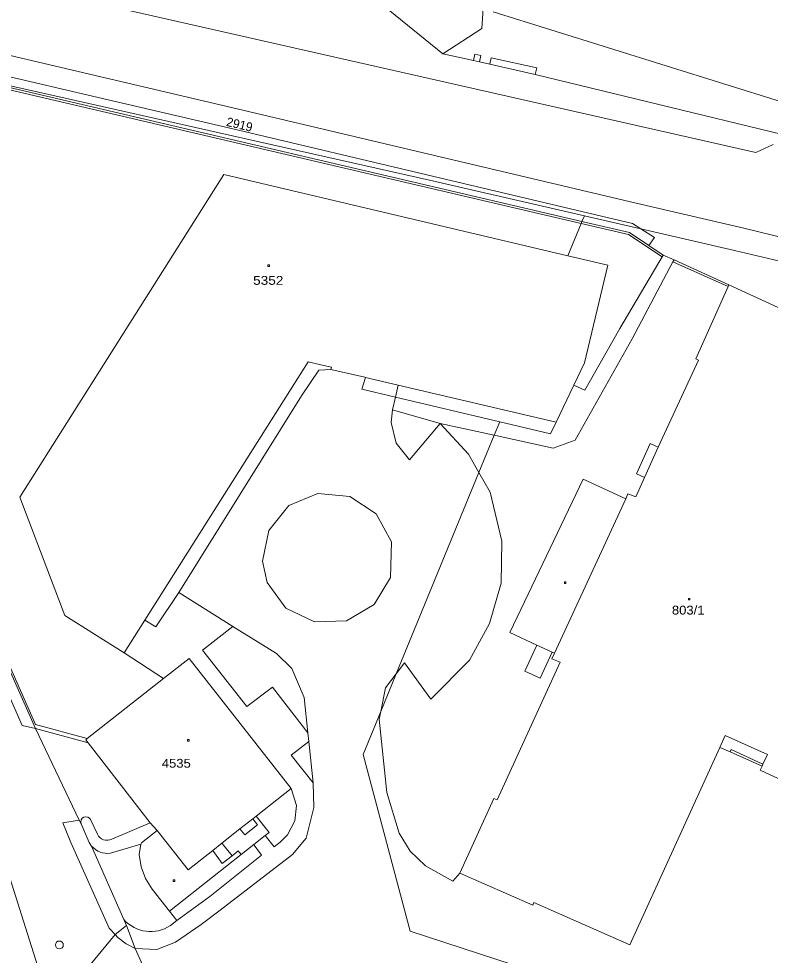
# Model space of a CAD drawing. Extents: x -630464 to -630140, y -1004543 to -1004208.
# Drawn here: x -630402.7 to -630330.5, y -1004346.3 to -1004256.3 of the extents above; entities that cross this region are included whole.
import ezdxf

# ---------------------------------------------------------------- set-up
doc = ezdxf.new("R2010")
doc.units = 0
doc.header["$LTSCALE"] = 0.34
for name, color, linetype, lineweight in [('1', 7, 'Continuous', 13), ('2', 7, 'Continuous', 13), ('25', 7, 'Continuous', 13), ('28', 7, 'Continuous', 13)]:
    doc.layers.add(name, color=color, linetype=linetype, lineweight=lineweight)
doc.layers.add('14', color=7, linetype='Continuous')
doc.layers.add('15', color=7, linetype='Continuous')

msp = doc.modelspace()

# ---------------------------------------------------------------- linework, layer by layer
at = {"layer": '1'}
for p, q in [((-630358.18, -1004257.25), (-630356.54, -1004231.37)), ((-630361.95, -1004259.68), (-630358.18, -1004257.25)), ((-630361.95, -1004259.68), (-630359, -1004260.33)), ((-630408.19, -1004261.71), (-630363.23, -1004271.82)), ((-630394.38, -1004262), (-630381.7, -1004264.98)), ((-630363.23, -1004271.82), (-630348.34, -1004275.25)), ((-630349.92, -1004279.08), (-630348.64, -1004275.98)), ((-630342.92, -1004276.5), (-630333.92, -1004278.57)), ((-630349.92, -1004279.08), (-630346.1, -1004279.98)), ((-630333.92, -1004278.57), (-630314.14, -1004283.28)), ((-630348.33, -1004289.39), (-630346.1, -1004279.98)), ((-630349.35, -1004291.51), (-630348.33, -1004289.39)), ((-630369.72, -1004291.92), (-630369.38, -1004290.78)), ((-630369.45, -1004290.77), (-630369.38, -1004290.78)), ((-630369.72, -1004291.92), (-630366.5, -1004292.68)), ((-630387.32, -1004311.45), (-630375.53, -1004292.54)), ((-630366.5, -1004292.68), (-630356.47, -1004295.05)), ((-630389.53, -1004314.74), (-630387.32, -1004311.45)), ((-630392.55, -1004317.25), (-630390.56, -1004314.1)), ((-630390.56, -1004314.1), (-630389.53, -1004314.74)), ((-630369.6, -1004327.01), (-630365.09, -1004344)), ((-630379.88, -1004332.94), (-630376.52, -1004330.29)), ((-630379.88, -1004332.94), (-630378.62, -1004334.51)), ((-630390.05, -1004333.58), (-630389.39, -1004334.31)), ((-630379, -1004334.81), (-630378.62, -1004334.51)), ((-630388.2, -1004342.09), (-630381.31, -1004336.63)), ((-630390.5, -1004338.94), (-630389.87, -1004339.97)), ((-630389.87, -1004339.97), (-630388.2, -1004342.09)), ((-630392.58, -1004342.89), (-630392.33, -1004343.45)), ((-630365.09, -1004344), (-630343.21, -1004351.12)), ((-630397.75, -1004349.57), (-630393.43, -1004344.32))]:
    msp.add_line(p, q, dxfattribs=at)
for points in [[(-630396.18, -1004252.07), (-630386.63, -1004248.4), (-630371.62, -1004251.8), (-630361.95, -1004259.68)], [(-630421.48, -1004257.69), (-630421.1, -1004257.42), (-630418.9, -1004256.48), (-630418.37, -1004256.39), (-630417.22, -1004256.61), (-630408.43, -1004258.7), (-630394.38, -1004262)], [(-630359, -1004260.33), (-630358.43, -1004260.46), (-630357.43, -1004260.68)], [(-630357.43, -1004260.68), (-630353.06, -1004261.66), (-630329.31, -1004267.44), (-630320.75, -1004269.74)], [(-630381.7, -1004264.98), (-630362.75, -1004269.45), (-630343.38, -1004274.04), (-630333.03, -1004276.43), (-630303.66, -1004283.61)], [(-630402.58, -1004302.3), (-630382.99, -1004271.28), (-630349.92, -1004279.08)], [(-630348.64, -1004275.98), (-630348.57, -1004275.81), (-630348.34, -1004275.25), (-630342.92, -1004276.5)], [(-630375.53, -1004292.54), (-630373.84, -1004290.08), (-630372.7, -1004290.01), (-630369.45, -1004290.77)], [(-630416.37, -1004290.21), (-630413.84, -1004296.07), (-630407.49, -1004310.15), (-630401.09, -1004324.53), (-630396.87, -1004333.33), (-630396.7, -1004333.68), (-630395.91, -1004335.47), (-630395.69, -1004335.82), (-630392.58, -1004342.89)], [(-630369.6, -1004327.01), (-630367.91, -1004322.89), (-630366.41, -1004319.26), (-630358.47, -1004299.92), (-630357, -1004296.34), (-630356.47, -1004295.05), (-630351.59, -1004296.2), (-630351.06, -1004295.08), (-630349.35, -1004291.51)], [(-630402.58, -1004302.3), (-630398.27, -1004313.66), (-630392.55, -1004317.25)], [(-630396.24, -1004325.6), (-630396.1, -1004325.48), (-630388.77, -1004319.7), (-630386.31, -1004317.78), (-630376.52, -1004330.29)], [(-630396.24, -1004325.6), (-630396.03, -1004325.9), (-630390.05, -1004333.58)], [(-630391.11, -1004336.62), (-630390.95, -1004335.65), (-630390.9, -1004335.51), (-630389.39, -1004334.31)], [(-630381.31, -1004336.63), (-630380.11, -1004335.68), (-630379, -1004334.81)], [(-630431.57, -1004347.96), (-630430.78, -1004347.84), (-630408.36, -1004344.42), (-630404.14, -1004336.97), (-630403.55, -1004338.86), (-630399.75, -1004350.85), (-630399.53, -1004351.54)], [(-630391.11, -1004336.62), (-630390.94, -1004337.81), (-630390.5, -1004338.94)], [(-630393.43, -1004344.32), (-630392.33, -1004343.45), (-630391.49, -1004345.66)], [(-630391.49, -1004345.66), (-630390.2, -1004348.57), (-630360.7, -1004381.74)]]:
    msp.add_lwpolyline(points, dxfattribs=at)
at = {"layer": '2'}
for p, q in [((-630416.92, -1004249.88), (-630331.87, -1004269.15)), ((-630357.09, -1004255.65), (-630329.39, -1004264.29)), ((-630358.43, -1004260.46), (-630358.29, -1004259.83)), ((-630357.43, -1004260.68), (-630357.29, -1004260.05)), ((-630357.29, -1004260.05), (-630352.92, -1004261.02)), ((-630408.68, -1004260.69), (-630395.06, -1004263.89)), ((-630353.06, -1004261.66), (-630352.92, -1004261.02)), ((-630409.01, -1004261.64), (-630348.57, -1004275.81)), ((-630408.92, -1004261.88), (-630348.64, -1004275.98)), ((-630395.06, -1004263.89), (-630382.13, -1004266.9)), ((-630382.13, -1004266.9), (-630362.92, -1004271.45)), ((-630331.87, -1004269.15), (-630330.2, -1004268.41)), ((-630362.92, -1004271.45), (-630343.72, -1004275.99)), ((-630348.64, -1004275.98), (-630344.1, -1004277.05)), ((-630348.57, -1004275.81), (-630344.02, -1004276.86)), ((-630343.72, -1004275.99), (-630342.92, -1004276.5)), ((-630342.92, -1004276.5), (-630341.61, -1004277.32)), ((-630344.1, -1004277.05), (-630340.87, -1004279.19)), ((-630344.02, -1004276.86), (-630342.14, -1004278.11)), ((-630342.14, -1004278.11), (-630341.61, -1004277.32)), ((-630342.14, -1004278.11), (-630340.77, -1004279.02)), ((-630344.94, -1004286.07), (-630340.87, -1004279.19)), ((-630343.74, -1004287.07), (-630339.83, -1004279.68)), ((-630339.83, -1004279.68), (-630339.72, -1004279.47)), ((-630339.83, -1004279.68), (-630334.51, -1004282.03)), ((-630339.72, -1004279.47), (-630334.45, -1004281.89)), ((-630337.64, -1004288.99), (-630334.51, -1004282.03)), ((-630348.29, -1004292.01), (-630344.94, -1004286.07)), ((-630349.21, -1004296.8), (-630343.74, -1004287.07)), ((-630390.56, -1004314.1), (-630374.88, -1004289.28)), ((-630374.88, -1004289.28), (-630373.66, -1004289.57)), ((-630337.64, -1004288.99), (-630337.37, -1004289.11)), ((-630373.66, -1004289.57), (-630372.65, -1004289.8)), ((-630372.7, -1004290.01), (-630372.65, -1004289.8)), ((-630369.38, -1004290.78), (-630366.22, -1004291.52)), ((-630366.5, -1004292.68), (-630366.22, -1004291.52)), ((-630366.22, -1004291.52), (-630351.06, -1004295.08)), ((-630349.35, -1004291.51), (-630348.29, -1004292.01)), ((-630366.79, -1004293.91), (-630366.5, -1004292.68)), ((-630366.92, -1004295.11), (-630366.79, -1004293.91)), ((-630366.79, -1004293.91), (-630362.19, -1004295.2)), ((-630366.92, -1004295.11), (-630366.43, -1004297.09)), ((-630365.14, -1004298.71), (-630362.19, -1004295.2)), ((-630362.19, -1004295.2), (-630357, -1004296.34)), ((-630362.19, -1004295.2), (-630359.48, -1004298.15)), ((-630357, -1004296.34), (-630351.33, -1004297.58)), ((-630366.43, -1004297.09), (-630365.14, -1004298.71)), ((-630351.33, -1004297.58), (-630349.21, -1004296.8)), ((-630343.34, -1004300.04), (-630342.03, -1004297.12)), ((-630359.48, -1004298.15), (-630358.47, -1004299.92)), ((-630342.57, -1004300.39), (-630341.26, -1004297.47)), ((-630358.47, -1004299.92), (-630357.39, -1004301.82)), ((-630343.34, -1004300.04), (-630342.57, -1004300.39)), ((-630355.49, -1004315.31), (-630348.45, -1004300.55)), ((-630348.45, -1004300.55), (-630344.37, -1004302.44)), ((-630343.4, -1004302.26), (-630342.57, -1004300.39)), ((-630357.39, -1004301.82), (-630356.26, -1004306.53)), ((-630376.75, -1004303.1), (-630373.94, -1004301.92)), ((-630373.94, -1004301.92), (-630370.88, -1004302.21)), ((-630370.88, -1004302.21), (-630368.33, -1004303.9)), ((-630351.22, -1004317.28), (-630344.37, -1004302.44)), ((-630344.37, -1004302.44), (-630344.15, -1004301.96)), ((-630344.15, -1004301.96), (-630343.4, -1004302.26)), ((-630378.66, -1004305.5), (-630376.75, -1004303.1)), ((-630368.33, -1004303.9), (-630366.86, -1004306.59)), ((-630379.27, -1004308.45), (-630378.66, -1004305.5)), ((-630366.96, -1004310.01), (-630366.86, -1004306.59)), ((-630356.35, -1004310.54), (-630356.26, -1004306.53)), ((-630379.27, -1004308.45), (-630378.81, -1004310.48)), ((-630407.31, -1004310.07), (-630401.07, -1004324.14)), ((-630378.81, -1004310.48), (-630377.02, -1004312.96)), ((-630368.55, -1004312.6), (-630366.96, -1004310.01)), ((-630357.45, -1004314.42), (-630356.35, -1004310.54)), ((-630387.32, -1004311.45), (-630382.11, -1004314.71)), ((-630371.21, -1004314.16), (-630368.55, -1004312.6)), ((-630377.02, -1004312.96), (-630374.26, -1004314.28)), ((-630374.26, -1004314.28), (-630371.21, -1004314.16)), ((-630359.38, -1004317.94), (-630357.45, -1004314.42)), ((-630385.03, -1004316.98), (-630382.11, -1004314.71)), ((-630382.11, -1004314.71), (-630377.92, -1004317.31)), ((-630355.49, -1004315.31), (-630352.9, -1004316.5)), ((-630385.03, -1004316.98), (-630380.76, -1004322.41)), ((-630354.05, -1004319), (-630352.9, -1004316.5)), ((-630352.9, -1004316.5), (-630351.45, -1004317.17)), ((-630352.6, -1004319.67), (-630351.45, -1004317.17)), ((-630351.45, -1004317.17), (-630351.22, -1004317.28)), ((-630392.55, -1004317.25), (-630388.77, -1004319.7)), ((-630377.92, -1004317.31), (-630376.44, -1004318.74)), ((-630363.1, -1004321.69), (-630359.38, -1004317.94)), ((-630351.47, -1004317.82), (-630351.22, -1004317.28)), ((-630351.47, -1004317.82), (-630350.66, -1004318.14)), ((-630376.44, -1004318.74), (-630375.27, -1004321.54)), ((-630366.41, -1004319.26), (-630365.61, -1004318.21)), ((-630365.61, -1004318.21), (-630363.1, -1004321.69)), ((-630356.71, -1004331.37), (-630350.66, -1004318.14)), ((-630367.46, -1004320.62), (-630366.41, -1004319.26)), ((-630354.05, -1004319), (-630352.6, -1004319.67)), ((-630380.76, -1004322.41), (-630378.31, -1004320.55)), ((-630378.31, -1004320.55), (-630374.91, -1004324.93)), ((-630375.27, -1004321.54), (-630374.91, -1004324.93)), ((-630402.35, -1004324.23), (-630401.09, -1004324.53)), ((-630401.07, -1004324.14), (-630396.1, -1004325.48)), ((-630368.05, -1004323.62), (-630367.33, -1004330.68)), ((-630401.09, -1004324.53), (-630396.03, -1004325.9)), ((-630374.91, -1004324.93), (-630374.83, -1004325.78)), ((-630376.5, -1004327.07), (-630374.83, -1004325.78)), ((-630374.83, -1004325.78), (-630374.41, -1004329.75)), ((-630376.5, -1004327.07), (-630374.41, -1004329.75)), ((-630343.96, -1004345.31), (-630335.33, -1004326.34)), ((-630334.33, -1004326.75), (-630335.33, -1004326.34)), ((-630334.33, -1004326.75), (-630334.24, -1004326.54)), ((-630334.33, -1004326.75), (-630331.27, -1004328.15)), ((-630334.24, -1004326.54), (-630331.18, -1004327.94)), ((-630331.18, -1004327.94), (-630330.76, -1004327.03)), ((-630331.27, -1004328.15), (-630331.18, -1004327.94)), ((-630331.44, -1004328.53), (-630331.27, -1004328.15)), ((-630331.44, -1004328.53), (-630326.84, -1004330.65)), ((-630374.41, -1004329.75), (-630374.35, -1004332.11)), ((-630376.52, -1004330.29), (-630376, -1004331.92)), ((-630367.33, -1004330.68), (-630366.15, -1004334.59)), ((-630360.32, -1004338.42), (-630357.03, -1004331.24)), ((-630357.03, -1004331.24), (-630356.71, -1004331.37)), ((-630376.16, -1004333.4), (-630376, -1004331.92)), ((-630375.06, -1004335.05), (-630374.35, -1004332.11)), ((-630398.45, -1004333.59), (-630396.87, -1004333.33)), ((-630395.78, -1004333.28), (-630395.13, -1004334.68)), ((-630381.43, -1004334.16), (-630380.21, -1004333.2)), ((-630380.21, -1004333.2), (-630379.88, -1004332.94)), ((-630380.21, -1004333.2), (-630379.74, -1004333.79)), ((-630393.75, -1004335.16), (-630390.05, -1004333.58)), ((-630383.16, -1004335.53), (-630381.43, -1004334.16)), ((-630381.43, -1004334.16), (-630380.96, -1004334.75)), ((-630380.96, -1004334.75), (-630379.74, -1004333.79)), ((-630376.85, -1004334.73), (-630376.16, -1004333.4)), ((-630389.39, -1004334.31), (-630386.41, -1004338.1)), ((-630379, -1004334.81), (-630378.15, -1004335.88)), ((-630377.57, -1004335.43), (-630376.85, -1004334.73)), ((-630376.37, -1004336.62), (-630375.06, -1004335.05)), ((-630366.15, -1004334.59), (-630365.07, -1004336.31)), ((-630393.88, -1004336.51), (-630390.95, -1004335.65)), ((-630384.05, -1004336.24), (-630383.16, -1004335.53)), ((-630383.16, -1004335.53), (-630383.13, -1004335.57)), ((-630378.15, -1004335.88), (-630377.57, -1004335.43)), ((-630386.41, -1004338.1), (-630384.05, -1004336.24)), ((-630384.34, -1004340.68), (-630379.35, -1004336.69)), ((-630384.05, -1004336.24), (-630383.14, -1004337.5)), ((-630383.34, -1004341.99), (-630376.37, -1004336.62)), ((-630383.14, -1004337.5), (-630382.18, -1004336.75)), ((-630381.59, -1004336.28), (-630381.31, -1004336.63)), ((-630365.07, -1004336.31), (-630363.62, -1004337.71)), ((-630363.62, -1004337.71), (-630360.98, -1004339.19)), ((-630360.98, -1004339.19), (-630360.32, -1004338.42)), ((-630360.32, -1004338.42), (-630353.28, -1004341.51)), ((-630387.51, -1004342.98), (-630384.34, -1004340.68)), ((-630353.28, -1004341.51), (-630353.19, -1004341.25)), ((-630353.19, -1004341.25), (-630343.96, -1004345.31)), ((-630388.2, -1004342.09), (-630387.51, -1004342.98)), ((-630385.15, -1004343.35), (-630383.34, -1004341.99)), ((-630388.12, -1004343.46), (-630387.51, -1004342.98)), ((-630394.01, -1004343.71), (-630393.43, -1004344.32)), ((-630387.63, -1004345.05), (-630385.15, -1004343.35)), ((-630389.43, -1004345.76), (-630387.63, -1004345.05)), ((-630392.38, -1004345.21), (-630391.49, -1004345.66)), ((-630391.49, -1004345.66), (-630389.43, -1004345.76))]:
    msp.add_line(p, q, dxfattribs=at)
for points in [[(-630359, -1004260.33), (-630358.86, -1004259.7), (-630358.29, -1004259.83)], [(-630427.64, -1004266.74), (-630427.45, -1004267.49), (-630427.28, -1004267.99), (-630427.06, -1004267.9), (-630402.35, -1004324.23)], [(-630340.87, -1004279.19), (-630340.77, -1004279.02), (-630339.72, -1004279.47)], [(-630334.51, -1004282.03), (-630334.45, -1004281.89), (-630327.34, -1004285.15)], [(-630342.03, -1004297.12), (-630341.26, -1004297.47), (-630337.37, -1004289.11)], [(-630368.05, -1004323.62), (-630367.91, -1004322.89), (-630367.46, -1004320.62)], [(-630335.33, -1004326.34), (-630334.81, -1004325.2), (-630330.76, -1004327.03)], [(-630398.45, -1004333.59), (-630397.69, -1004335.48), (-630394.01, -1004343.71)], [(-630383.13, -1004335.57), (-630382.18, -1004336.75), (-630381.59, -1004336.28)], [(-630380.11, -1004335.68), (-630380.07, -1004335.73), (-630379.35, -1004336.69)], [(-630393.43, -1004344.32), (-630393.17, -1004344.6), (-630392.38, -1004345.21)]]:
    msp.add_lwpolyline(points, dxfattribs=at)
for centre, radius, start, end in [((-630396.233, -1004333.497), 0.502, 25.57273, 201.42439), ((-630394.211, -1004334.26), 1.011, 204.54231, 297.09967), ((-630394.161, -1004334.528), 2.002, 220.20015, 278.06461), ((-630390.025, -1004340.629), 3.412, 221.50164, 303.93221)]:
    msp.add_arc(centre, radius, start, end, dxfattribs=at)
at = {"layer": '25'}
for points in [[(-630378.74, -1004279.96), (-630378.59, -1004279.96), (-630378.59, -1004280.11), (-630378.74, -1004280.11)], [(-630350.26, -1004310.42), (-630350.11, -1004310.42), (-630350.11, -1004310.57), (-630350.26, -1004310.57)], [(-630338.35, -1004312.02), (-630338.2, -1004312.02), (-630338.2, -1004312.17), (-630338.35, -1004312.17)], [(-630386.46, -1004325.59), (-630386.31, -1004325.59), (-630386.31, -1004325.74), (-630386.46, -1004325.74)], [(-630387.85, -1004339.06), (-630387.7, -1004339.06), (-630387.7, -1004339.21), (-630387.85, -1004339.21)]]:
    msp.add_lwpolyline(points, close=True, dxfattribs=at)
at = {"layer": '28'}
for radius in [0.375, 0.005]:
    msp.add_circle((-630398.78, -1004345.32), radius, dxfattribs=at)

# ---------------------------------------------------------------- texts
at = {"layer": '14'}
msp.add_text('2919', height=0.85, rotation=346.579, dxfattribs=at).set_placement((-630382.8, -1004266.59))
at = {"layer": '15'}
for s, width, p in [('5352', 1.15, (-630380.17, -1004281.88)), ('803/1', 1.1, (-630339.93, -1004313.57)), ('4535', 1.1, (-630388.94, -1004328.29))]:
    msp.add_text(s, height=0.85, dxfattribs=dict(at, width=width)).set_placement(p)

doc.saveas('drawing.dxf')
